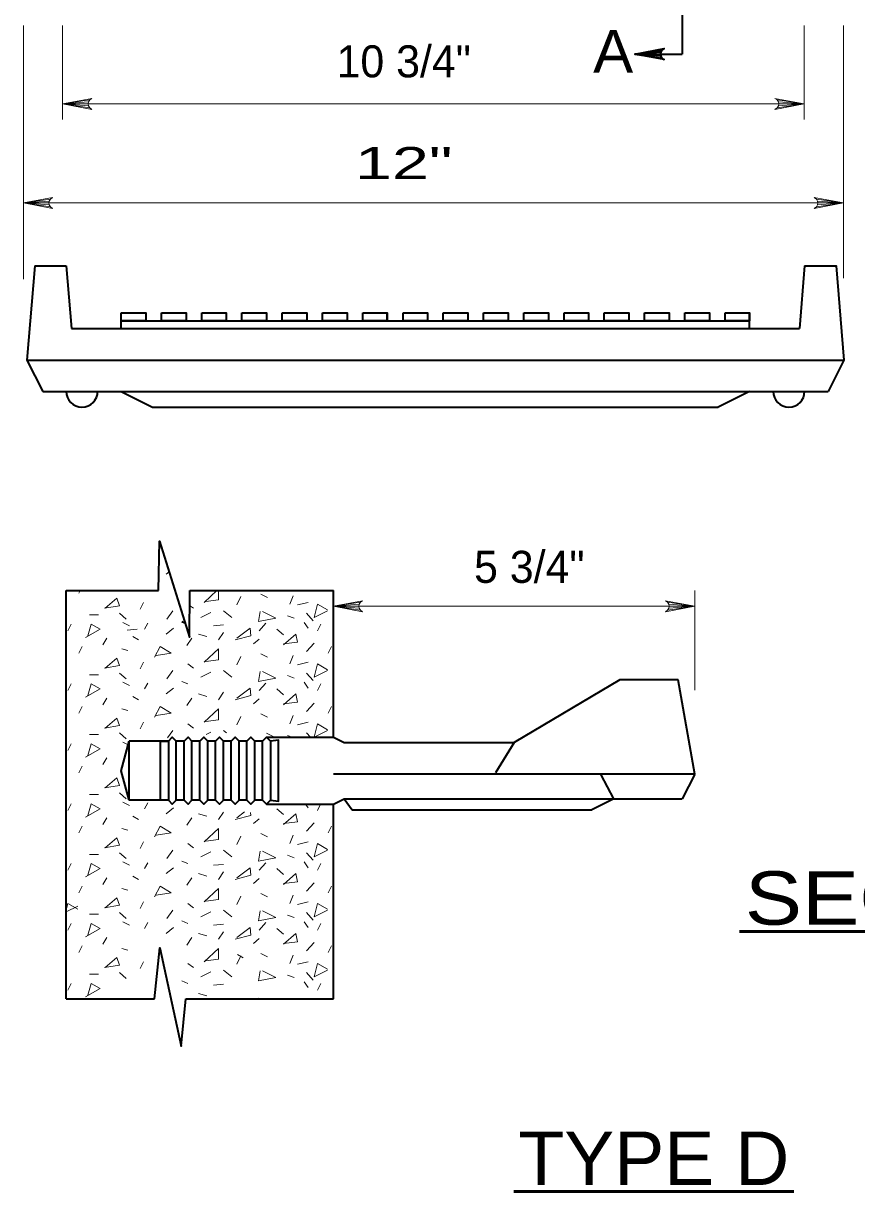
# Model space of a CAD drawing. Extents: x 15 to 140, y -57 to 117.
# Drawn here: x 97.08 to 123.6, y -0.87 to 36.32 of the extents above; entities that cross this region are included whole.
import ezdxf
from ezdxf.enums import TextEntityAlignment as Align

# ---------------------------------------------------------------- set-up
doc = ezdxf.new("R2010")
doc.units = 0
doc.header["$LTSCALE"] = 0.41
for name, color, linetype, lineweight in [('1', 7, 'Continuous', 35), ('10', 7, 'Continuous', 13), ('12', 7, 'Continuous', 53), ('13', 7, 'Continuous', 53), ('6', 7, 'Continuous', 13)]:
    doc.layers.add(name, color=color, linetype=linetype, lineweight=lineweight)

msp = doc.modelspace()

# ---------------------------------------------------------------- linework, layer by layer
at = {"layer": '1'}
for p, q in [((97.4464, 28.6016), (97.1964, 25.6016)), ((97.4464, 28.6016), (98.4464, 28.6016)), ((98.4464, 28.6016), (98.6131, 26.6016)), ((121.9464, 28.6016), (121.7798, 26.6016)), ((100.1964, 26.8516), (120.1964, 26.8516)), ((108.6655, 26.8516), (108.6655, 27.1016)), ((120.1964, 26.6016), (120.1964, 27.1016)), ((98.6131, 26.6016), (121.7798, 26.6016)), ((97.1964, 25.6016), (123.1964, 25.6016)), ((97.1964, 25.6016), (97.6964, 24.6016)), ((123.1964, 25.6016), (122.6964, 24.6016)), ((97.6964, 24.6016), (122.6964, 24.6016)), ((100.1964, 24.6016), (101.1964, 24.1016)), ((120.1964, 24.6016), (119.1964, 24.1016)), ((101.1964, 24.1016), (119.1964, 24.1016)), ((98.448, 5.2657), (98.448, 18.2657)), ((98.448, 18.2657), (101.3862, 18.2657)), ((102.3766, 18.2657), (106.948, 18.2657)), ((106.948, 13.5955), (106.948, 18.2657)), ((102.126, 17.2785), (102.2236, 17.2366)), ((116.0612, 15.4252), (112.698, 13.4252)), ((117.919, 15.4252), (116.0612, 15.4252)), ((118.448, 12.4252), (117.919, 15.4252)), ((100.448, 11.5907), (100.448, 13.4705)), ((101.698, 13.4705), (100.448, 13.4705)), ((101.948, 11.5907), (101.948, 13.4705)), ((102.198, 13.4705), (101.948, 13.4705)), ((102.198, 11.5907), (102.198, 13.4705)), ((102.448, 11.5907), (102.448, 13.4705)), ((102.698, 13.4705), (102.448, 13.4705)), ((102.698, 11.5907), (102.698, 13.4705)), ((102.948, 11.5907), (102.948, 13.4705)), ((103.198, 13.4705), (102.948, 13.4705)), ((103.198, 11.5907), (103.198, 13.4705)), ((103.448, 11.5907), (103.448, 13.4705)), ((103.698, 13.4705), (103.448, 13.4705)), ((103.698, 11.5907), (103.698, 13.4705)), ((103.948, 11.5907), (103.948, 13.4705)), ((104.198, 13.4705), (103.948, 13.4705)), ((104.198, 11.5907), (104.198, 13.4705)), ((104.448, 11.5907), (104.448, 13.4705)), ((104.698, 13.4705), (104.448, 13.4705)), ((104.698, 11.5907), (104.698, 13.4705)), ((104.823, 13.5955), (106.948, 13.5955)), ((112.698, 13.4252), (112.1117, 12.4577)), ((118.448, 12.4252), (106.948, 12.4252)), ((115.8694, 11.636), (115.4681, 12.3993)), ((118.448, 12.4252), (118.0533, 11.636)), ((101.698, 11.5907), (100.448, 11.5907)), ((102.198, 11.5907), (101.948, 11.5907)), ((102.698, 11.5907), (102.448, 11.5907)), ((103.198, 11.5907), (102.948, 11.5907)), ((103.698, 11.5907), (103.448, 11.5907)), ((104.198, 11.5907), (103.948, 11.5907)), ((104.698, 11.5907), (104.448, 11.5907)), ((107.2904, 11.636), (107.5482, 11.286)), ((115.8694, 11.636), (115.1694, 11.286)), ((104.823, 11.4657), (106.948, 11.4657)), ((106.948, 5.2657), (106.948, 11.4657)), ((107.5482, 11.286), (115.1694, 11.286)), ((98.448, 5.2657), (101.2527, 5.2657)), ((102.2482, 5.2657), (106.948, 5.2657))]:
    msp.add_line(p, q, dxfattribs=at)
for points in [[(121.9464, 28.6016), (122.9464, 28.6016), (123.1964, 25.6016)], [(100.1964, 26.6016), (100.1964, 26.8516), (100.1964, 27.1016)], [(100.448, 11.5907), (100.198, 12.5306), (100.448, 13.4705)], [(101.698, 13.4705), (101.823, 13.5955), (101.948, 13.4705)], [(102.198, 13.4705), (102.323, 13.5955), (102.448, 13.4705)], [(102.698, 13.4705), (102.823, 13.5955), (102.948, 13.4705)], [(103.198, 13.4705), (103.323, 13.5955), (103.448, 13.4705)], [(103.698, 13.4705), (103.823, 13.5955), (103.948, 13.4705)], [(104.198, 13.4705), (104.323, 13.5955), (104.448, 13.4705)], [(104.698, 13.4705), (104.823, 13.5955), (104.948, 13.4705)], [(106.948, 13.5955), (107.2904, 13.4252), (112.698, 13.4252)], [(101.698, 11.5907), (101.823, 11.4657), (101.948, 11.5907)], [(102.198, 11.5907), (102.323, 11.4657), (102.448, 11.5907)], [(102.698, 11.5907), (102.823, 11.4657), (102.948, 11.5907)], [(103.198, 11.5907), (103.323, 11.4657), (103.448, 11.5907)], [(103.698, 11.5907), (103.823, 11.4657), (103.948, 11.5907)], [(104.198, 11.5907), (104.323, 11.4657), (104.448, 11.5907)], [(104.698, 11.5907), (104.823, 11.4657), (104.948, 11.5907)], [(106.948, 11.4657), (107.2904, 11.636), (118.0533, 11.636)]]:
    msp.add_lwpolyline(points, dxfattribs=at)
for points in [[(100.1964, 27.1016), (100.9777, 27.1016), (100.9777, 26.8516), (100.1964, 26.8516)], [(101.4777, 27.1016), (102.259, 27.1016), (102.259, 26.8516), (101.4777, 26.8516)], [(102.759, 27.1016), (103.5403, 27.1016), (103.5403, 26.8516), (102.759, 26.8516)], [(104.0403, 27.1016), (104.8216, 27.1016), (104.8216, 26.8516), (104.0403, 26.8516)], [(105.3216, 27.1016), (106.1029, 27.1016), (106.1029, 26.8516), (105.3216, 26.8516)], [(106.6029, 27.1016), (107.3842, 27.1016), (107.3842, 26.8516), (106.6029, 26.8516)], [(107.8842, 27.1016), (108.6655, 27.1016), (108.6655, 26.8516), (107.8842, 26.8516)], [(109.1655, 27.1016), (109.9468, 27.1016), (109.9468, 26.8516), (109.1655, 26.8516)], [(110.4468, 27.1016), (111.2281, 27.1016), (111.2281, 26.8516), (110.4468, 26.8516)], [(111.7281, 27.1016), (112.5094, 27.1016), (112.5094, 26.8516), (111.7281, 26.8516)], [(113.0094, 27.1016), (113.7907, 27.1016), (113.7907, 26.8516), (113.0094, 26.8516)], [(114.2907, 27.1016), (115.072, 27.1016), (115.072, 26.8516), (114.2907, 26.8516)], [(115.572, 27.1016), (116.3533, 27.1016), (116.3533, 26.8516), (115.572, 26.8516)], [(116.8533, 27.1016), (117.6346, 27.1016), (117.6346, 26.8516), (116.8533, 26.8516)], [(118.1346, 27.1016), (118.9159, 27.1016), (118.9159, 26.8516), (118.1346, 26.8516)], [(119.4151, 27.1016), (120.1964, 27.1016), (120.1964, 26.8516), (119.4151, 26.8516)], [(101.448, 11.5907), (101.448, 13.4705), (101.698, 13.4705), (101.698, 11.5907)], [(104.948, 11.5907), (105.198, 11.5594), (105.198, 13.5017), (104.948, 13.4705)]]:
    msp.add_lwpolyline(points, close=True, dxfattribs=at)
for centre in [(98.9464, 24.6016), (121.4464, 24.6016)]:
    msp.add_arc(centre, 0.5, 180, 0, dxfattribs=at)
at = {"layer": '10', "lineweight": 35}
for p in [(118.0471, 40.3391), (116.5471, 35.3391)]:
    msp.add_line(p, (118.0471, 35.3391), dxfattribs=at)
at = {"layer": '10'}
for p, q in [((97.082, 36.2556), (97.082, 28.1747)), ((98.332, 36.2556), (98.332, 33.2556)), ((121.9346, 36.2556), (121.9346, 33.2556)), ((123.1846, 36.2556), (123.1846, 28.2123)), ((98.332, 33.7556), (121.9346, 33.7556)), ((97.082, 30.6016), (123.1846, 30.6016)), ((118.448, 15.0913), (118.448, 18.2657)), ((106.948, 17.7657), (118.448, 17.7657))]:
    msp.add_line(p, q, dxfattribs=at)
at = {"layer": '10', "lineweight": 35}
for points in [[(116.5471, 35.3391), (117.4791, 35.5139), (117.4073, 35.4641), (117.3703, 35.4016), (117.3596, 35.3391), (117.3703, 35.2766), (117.4073, 35.2141), (117.4791, 35.1644), (116.5471, 35.3391), (117.4073, 35.2141), (117.3703, 35.2766), (116.5471, 35.3391), (117.3596, 35.3391), (117.3703, 35.4016), (116.5471, 35.3391), (117.4073, 35.4641)], [(101.3862, 18.2657), (101.4157, 19.8375), (102.3652, 16.7808), (102.3766, 18.2657)], [(101.2527, 5.2657), (101.4258, 6.8915), (102.1052, 3.7637), (102.2482, 5.2657)]]:
    msp.add_lwpolyline(points, dxfattribs=at)
at = {"layer": '10'}
for points in [[(98.332, 33.7556), (99.2641, 33.9303), (99.1923, 33.8806), (99.1553, 33.8181), (99.1445, 33.7556), (99.1553, 33.6931), (99.1923, 33.6306), (99.2641, 33.5808), (98.332, 33.7556), (99.1923, 33.6306), (99.1553, 33.6931), (98.332, 33.7556), (99.1445, 33.7556), (99.1553, 33.8181), (98.332, 33.7556), (99.1923, 33.8806)], [(121.9346, 33.7556), (121.0026, 33.5808), (121.0744, 33.6306), (121.1114, 33.6931), (121.1221, 33.7556), (121.1114, 33.8181), (121.0744, 33.8806), (121.0026, 33.9303), (121.9346, 33.7556), (121.0744, 33.8806), (121.1114, 33.8181), (121.9346, 33.7556), (121.1221, 33.7556), (121.1114, 33.6931), (121.9346, 33.7556), (121.0744, 33.6306)], [(97.082, 30.6016), (98.0141, 30.7764), (97.9423, 30.7266), (97.9053, 30.6641), (97.8945, 30.6016), (97.9053, 30.5391), (97.9423, 30.4766), (98.0141, 30.4268), (97.082, 30.6016), (97.9423, 30.4766), (97.9053, 30.5391), (97.082, 30.6016), (97.8945, 30.6016), (97.9053, 30.6641), (97.082, 30.6016), (97.9423, 30.7266)], [(123.1846, 30.6016), (122.2526, 30.4268), (122.3244, 30.4766), (122.3614, 30.5391), (122.3721, 30.6016), (122.3614, 30.6641), (122.3244, 30.7266), (122.2526, 30.7764), (123.1846, 30.6016), (122.3244, 30.7266), (122.3614, 30.6641), (123.1846, 30.6016), (122.3721, 30.6016), (122.3614, 30.5391), (123.1846, 30.6016), (122.3244, 30.4766)], [(106.948, 17.7657), (107.88, 17.9404), (107.8082, 17.8907), (107.7712, 17.8282), (107.7605, 17.7657), (107.7712, 17.7032), (107.8082, 17.6407), (107.88, 17.5909), (106.948, 17.7657), (107.8082, 17.6407), (107.7712, 17.7032), (106.948, 17.7657), (107.7605, 17.7657), (107.7712, 17.8282), (106.948, 17.7657), (107.8082, 17.8907)], [(118.448, 17.7657), (117.5159, 17.5909), (117.5877, 17.6407), (117.6247, 17.7032), (117.6355, 17.7657), (117.6247, 17.8282), (117.5877, 17.8907), (117.5159, 17.9404), (118.448, 17.7657), (117.5877, 17.8907), (117.6247, 17.8282), (118.448, 17.7657), (117.6355, 17.7657), (117.6247, 17.7032), (118.448, 17.7657), (117.5877, 17.6407)]]:
    msp.add_lwpolyline(points, dxfattribs=at)
at = {"layer": '12'}
for p, q in [((119.8744, 7.4159), (137.6453, 7.4159)), ((112.6908, -0.8679), (121.6056, -0.8679))]:
    msp.add_line(p, q, dxfattribs=at)
at = {"layer": '6'}
for p, q in [((101.7187, 18.8621), (101.623, 18.7876)), ((98.8865, 18.2657), (98.843, 18.1786)), ((100.3784, 18.2657), (100.4051, 18.2581)), ((103.2428, 18.2657), (102.8408, 17.8874)), ((100.8022, 17.6756), (100.9081, 17.8874)), ((103.8734, 17.808), (104.0058, 18.0727)), ((104.6412, 18.1522), (104.853, 18.0463)), ((105.6737, 18.0992), (105.5678, 17.8345)), ((106.1503, 17.8874), (105.8061, 17.808)), ((99.1872, 17.4903), (99.4784, 17.4903)), ((100.1403, 17.5432), (100.3521, 17.3579)), ((101.8348, 17.6227), (101.6494, 17.3579)), ((102.3729, 17.7905), (102.4967, 17.7021)), ((103.0526, 17.5697), (102.7349, 17.4109)), ((103.4498, 17.6227), (103.7145, 17.4109)), ((106.0974, 17.5432), (106.3092, 17.3049)), ((98.6047, 17.199), (98.4988, 16.9872)), ((100.2462, 17.252), (100.458, 17.1461)), ((100.9346, 17.0402), (101.0405, 17.2255)), ((103.1321, 17.1461), (103.4498, 17.1726)), ((104.5882, 16.9872), (104.8, 17.2255)), ((105.4884, 17.4638), (105.7002, 17.3844)), ((106.0179, 17.252), (106.1503, 17.0667)), ((106.5474, 17.199), (106.4415, 16.9872)), ((99.6108, 16.5372), (99.7432, 16.749)), ((100.3875, 17.0054), (100.7052, 17.0319)), ((100.5639, 16.8019), (100.7493, 16.696)), ((101.8612, 17.0667), (101.623, 16.8813)), ((102.4437, 16.749), (102.2849, 16.5107)), ((102.6555, 16.8813), (102.9203, 16.8019)), ((103.2909, 16.696), (103.4498, 16.9343)), ((105.1442, 17.0402), (105.356, 16.8549)), ((98.9489, 16.4842), (98.843, 16.2724)), ((100.2197, 16.4048), (100.4051, 16.3518)), ((104.4029, 16.5636), (104.5882, 16.7225)), ((106.3356, 16.5901), (106.0974, 16.3253)), ((106.8916, 16.4842), (106.7857, 16.2724)), ((103.8734, 15.9017), (104.0058, 16.1665)), ((104.6412, 16.2459), (104.853, 16.14)), ((105.6737, 16.193), (105.5678, 15.9282)), ((100.1403, 15.637), (100.3521, 15.4516)), ((100.8022, 15.7694), (100.9081, 15.9812)), ((101.8348, 15.7164), (101.6494, 15.4516)), ((102.3113, 15.9282), (102.4967, 15.7958)), ((103.0526, 15.6635), (102.7349, 15.5046)), ((103.4498, 15.7164), (103.7145, 15.5046)), ((106.1503, 15.9812), (105.8061, 15.9017)), ((106.0974, 15.637), (106.3092, 15.3987)), ((98.6047, 15.2928), (98.4988, 15.081)), ((99.1872, 15.584), (99.4784, 15.584)), ((100.2462, 15.3457), (100.458, 15.2398)), ((100.9346, 15.1339), (101.0405, 15.3193)), ((102.126, 15.3722), (102.3113, 15.2928)), ((104.5882, 15.081), (104.8, 15.3193)), ((105.4884, 15.5576), (105.7002, 15.4781)), ((106.0179, 15.3457), (106.1503, 15.1604)), ((106.5474, 15.2928), (106.4415, 15.081)), ((100.5639, 14.8957), (100.7493, 14.7898)), ((101.8612, 15.1604), (101.623, 14.9751)), ((102.6555, 14.9751), (102.9203, 14.8957)), ((103.2909, 14.7898), (103.4498, 15.028)), ((105.1442, 15.1339), (105.356, 14.9486)), ((98.9489, 14.5779), (98.843, 14.3661)), ((99.6108, 14.6309), (99.7432, 14.8427)), ((102.4437, 14.8427), (102.2849, 14.6044)), ((104.4029, 14.6574), (104.5882, 14.8162)), ((106.3356, 14.6839), (106.0974, 14.4191)), ((106.8916, 14.5779), (106.7857, 14.3661)), ((100.2197, 14.4985), (100.4051, 14.4456)), ((103.8734, 13.9955), (104.0058, 14.2602)), ((104.6412, 14.3397), (104.853, 14.2338)), ((105.6737, 14.2867), (105.5678, 14.022)), ((100.8022, 13.8631), (100.9081, 14.0749)), ((101.8348, 13.8102), (101.6699, 13.5747)), ((102.3113, 14.022), (102.4967, 13.8896)), ((103.4498, 13.8102), (103.5444, 13.7345)), ((106.1503, 14.0749), (105.8061, 13.9955)), ((99.1872, 13.6778), (99.4784, 13.6778)), ((100.1403, 13.7307), (100.3521, 13.5454)), ((100.2462, 13.4395), (100.417, 13.3541)), ((103.0526, 13.7572), (102.8968, 13.6793)), ((105.0705, 13.5955), (104.8176, 13.722)), ((105.4884, 13.6513), (105.6372, 13.5955)), ((106.0974, 13.7307), (106.2176, 13.5955)), ((98.6047, 13.3865), (98.4988, 13.1747)), ((98.9489, 12.6717), (98.843, 12.4599)), ((99.6108, 12.7247), (99.7432, 12.9365)), ((99.1872, 11.7715), (99.4784, 11.7715)), ((100.1403, 11.8245), (100.3521, 11.6391)), ((100.2462, 11.5332), (100.458, 11.4273)), ((98.6047, 11.4803), (98.4988, 11.2685)), ((100.9346, 11.3214), (101.0405, 11.5068)), ((101.8612, 11.3479), (101.623, 11.1626)), ((102.6555, 11.1626), (102.9203, 11.0832)), ((103.2909, 10.9773), (103.4498, 11.2155)), ((104.1234, 11.2177), (103.8734, 11.0302)), ((105.1442, 11.3214), (105.356, 11.1361)), ((106.0662, 11.4657), (106.1503, 11.3479)), ((106.5401, 11.4657), (106.4415, 11.2685)), ((99.6108, 10.8184), (99.7432, 11.0302)), ((100.5639, 11.0832), (100.7493, 10.9773)), ((102.4437, 11.0302), (102.2849, 10.7919)), ((104.4029, 10.8449), (104.5882, 11.0037)), ((106.3356, 10.8714), (106.0974, 10.6066)), ((98.9489, 10.7654), (98.843, 10.5536)), ((100.2197, 10.686), (100.4051, 10.6331)), ((103.8734, 10.183), (104.0058, 10.4477)), ((104.6412, 10.5272), (104.853, 10.4213)), ((105.6737, 10.4742), (105.5678, 10.2095)), ((106.8916, 10.7654), (106.7857, 10.5536)), ((100.8022, 10.0506), (100.9081, 10.2624)), ((102.3113, 10.2095), (102.4967, 10.0771)), ((106.1503, 10.2624), (105.8061, 10.183)), ((99.1872, 9.8653), (99.4784, 9.8653)), ((100.1403, 9.9182), (100.3521, 9.7329)), ((101.8348, 9.9977), (101.6494, 9.7329)), ((103.0526, 9.9447), (102.7349, 9.7859)), ((103.4498, 9.9977), (103.7145, 9.7859)), ((105.4884, 9.8388), (105.7002, 9.7594)), ((106.0974, 9.9182), (106.3092, 9.6799)), ((98.6047, 9.574), (98.4988, 9.3622)), ((100.2462, 9.627), (100.458, 9.5211)), ((100.9346, 9.4152), (101.0405, 9.6005)), ((101.8612, 9.4417), (101.623, 9.2563)), ((102.126, 9.6535), (102.3113, 9.574)), ((103.1321, 9.5211), (103.4498, 9.5476)), ((103.2909, 9.071), (103.4498, 9.3093)), ((104.5882, 9.3622), (104.8, 9.6005)), ((105.1442, 9.4152), (105.356, 9.2299)), ((106.0179, 9.627), (106.1503, 9.4417)), ((106.5474, 9.574), (106.4415, 9.3622)), ((99.6108, 8.9122), (99.7432, 9.124)), ((100.5639, 9.1769), (100.7493, 9.071)), ((102.4437, 9.124), (102.2849, 8.8857)), ((102.6555, 9.2563), (102.9203, 9.1769)), ((104.4029, 8.9386), (104.5882, 9.0975)), ((106.3356, 8.9651), (106.0974, 8.7003)), ((98.9489, 8.8592), (98.843, 8.6474)), ((100.2197, 8.7798), (100.4051, 8.7268)), ((104.6412, 8.6209), (104.853, 8.515)), ((105.6737, 8.568), (105.5678, 8.3032)), ((106.8916, 8.8592), (106.7857, 8.6474)), ((98.8165, 8.2193), (98.448, 8.035)), ((100.8022, 8.1444), (100.9081, 8.3562)), ((102.3113, 8.3032), (102.4967, 8.1708)), ((103.8734, 8.2767), (104.0058, 8.5415)), ((106.1503, 8.3562), (105.8061, 8.2767)), ((99.1872, 7.959), (99.4784, 7.959)), ((100.1403, 8.012), (100.3521, 7.8266)), ((101.8348, 8.0914), (101.6494, 7.8266)), ((103.0526, 8.0385), (102.7349, 7.8796)), ((103.4498, 8.0914), (103.7145, 7.8796)), ((105.4884, 7.9326), (105.7002, 7.8531)), ((106.0974, 8.012), (106.3092, 7.7737)), ((98.6047, 7.6678), (98.4988, 7.456)), ((100.2462, 7.7207), (100.458, 7.6148)), ((100.9346, 7.5089), (101.0405, 7.6943)), ((101.8612, 7.5354), (101.623, 7.3501)), ((102.126, 7.7472), (102.3113, 7.6678)), ((103.1321, 7.6148), (103.4498, 7.6413)), ((104.5882, 7.456), (104.8, 7.6943)), ((105.1442, 7.5089), (105.356, 7.3236)), ((106.0179, 7.7207), (106.1503, 7.5354)), ((106.5474, 7.6678), (106.4415, 7.456)), ((99.6108, 7.0059), (99.7432, 7.2177)), ((102.4437, 7.2177), (102.2849, 6.9794)), ((102.6555, 7.3501), (102.9203, 7.2707)), ((103.2909, 7.1648), (103.4498, 7.403)), ((104.4029, 7.0324), (104.5882, 7.1912)), ((98.9489, 6.9529), (98.843, 6.7411)), ((100.2197, 6.8735), (100.4051, 6.8206)), ((104.6412, 6.7147), (104.853, 6.6088)), ((106.3356, 7.0589), (106.0974, 6.7941)), ((106.8916, 6.9529), (106.7857, 6.7411)), ((100.8022, 6.2381), (100.9081, 6.4499)), ((102.3113, 6.397), (102.4967, 6.2646)), ((103.8734, 6.3705), (104.0058, 6.6352)), ((103.8966, 6.6821), (104.0819, 6.5762)), ((105.6737, 6.6617), (105.5678, 6.397)), ((106.1503, 6.4499), (105.8061, 6.3705)), ((99.1872, 6.0528), (99.4784, 6.0528)), ((100.1403, 6.1057), (100.3521, 5.9204)), ((103.0526, 6.1322), (102.7349, 5.9734)), ((103.4498, 6.1852), (103.7145, 5.9734)), ((105.4884, 6.0263), (105.7002, 5.9469)), ((106.0974, 6.1057), (106.3092, 5.8674)), ((98.6047, 5.7615), (98.4988, 5.5497)), ((102.126, 5.841), (102.3113, 5.7615)), ((103.1321, 5.7086), (103.4498, 5.7351)), ((106.0179, 5.8145), (106.1503, 5.6292)), ((106.5474, 5.7615), (106.4415, 5.5497)), ((102.6555, 5.4438), (102.9203, 5.3644)), ((104.5657, 5.2657), (104.5882, 5.285))]:
    msp.add_line(p, q, dxfattribs=at)
for points in [[(102.8938, 17.9139), (103.2909, 17.9668), (103.2909, 18.2657)], [(99.6638, 17.7021), (100.1403, 17.7815), (100.0609, 18.0198), (99.6902, 17.7021)], [(104.6147, 17.5962), (104.5618, 17.2785), (105.1178, 17.3844), (104.6941, 17.5962)], [(106.7592, 17.6227), (106.3356, 17.4109), (106.4415, 17.8345), (106.7592, 17.6491)], [(99.0548, 16.7754), (99.5314, 17.0402), (99.2401, 17.199), (99.1342, 16.8284)], [(103.8204, 16.696), (104.3235, 16.8284), (104.297, 17.0667), (103.8734, 16.749)], [(105.356, 16.5636), (105.8061, 16.6166), (105.7532, 16.8813), (105.356, 16.5372)], [(101.2523, 16.14), (101.4376, 16.4842), (101.7818, 16.2724), (101.3053, 16.193)], [(102.8938, 16.0076), (103.2909, 16.0606), (103.2909, 16.4048), (102.8408, 15.9812)], [(99.6638, 15.7958), (100.1403, 15.8753), (100.0609, 16.1135), (99.6902, 15.7958)], [(104.6147, 15.6899), (104.5618, 15.3722), (105.1178, 15.4781), (104.6941, 15.6899)], [(106.7592, 15.7164), (106.3356, 15.5046), (106.4415, 15.9282), (106.7592, 15.7429)], [(99.0548, 14.8692), (99.5314, 15.1339), (99.2401, 15.2928), (99.1342, 14.9221)], [(103.8204, 14.7898), (104.3235, 14.9221), (104.297, 15.1604), (103.8734, 14.8427)], [(105.356, 14.6574), (105.8061, 14.7103), (105.7532, 14.9751), (105.356, 14.6309)], [(101.2523, 14.2338), (101.4376, 14.5779), (101.7818, 14.3661), (101.3053, 14.2867)], [(99.6638, 13.8896), (100.1403, 13.969), (100.0609, 14.2073), (99.6902, 13.8896)], [(102.8938, 14.1014), (103.2909, 14.1543), (103.2909, 14.4985), (102.8408, 14.0749)], [(106.7592, 13.8102), (106.3356, 13.5984), (106.4415, 14.022), (106.7592, 13.8366)], [(99.0548, 12.9629), (99.5314, 13.2277), (99.2401, 13.3865), (99.1342, 13.0159)], [(99.6638, 11.9833), (100.1403, 12.0628), (100.0609, 12.301), (99.6902, 11.9833)], [(99.0548, 11.0567), (99.5314, 11.3214), (99.2401, 11.4803), (99.1342, 11.1096)], [(103.8204, 10.9773), (104.3235, 11.1096), (104.3136, 11.1984)], [(105.356, 10.8449), (105.8061, 10.8978), (105.7532, 11.1626), (105.356, 10.8184)], [(101.2523, 10.4213), (101.4376, 10.7654), (101.7818, 10.5536), (101.3053, 10.4742)], [(102.8938, 10.2889), (103.2909, 10.3418), (103.2909, 10.686), (102.8408, 10.2624)], [(99.6638, 10.0771), (100.1403, 10.1565), (100.0609, 10.3948), (99.6902, 10.0771)], [(106.7592, 9.9977), (106.3356, 9.7859), (106.4415, 10.2095), (106.7592, 10.0241)], [(104.6147, 9.9712), (104.5618, 9.6535), (105.1178, 9.7594), (104.6941, 9.9712)], [(99.0548, 9.1504), (99.5314, 9.4152), (99.2401, 9.574), (99.1342, 9.2034)], [(103.8204, 9.071), (104.3235, 9.2034), (104.297, 9.4417), (103.8734, 9.124)], [(105.356, 8.9386), (105.8061, 8.9916), (105.7532, 9.2563), (105.356, 8.9122)], [(101.2523, 8.515), (101.4376, 8.8592), (101.7818, 8.6474), (101.3053, 8.568)], [(102.8938, 8.3826), (103.2909, 8.4356), (103.2909, 8.7798), (102.8408, 8.3562)], [(98.448, 8.0998), (98.4988, 8.3032), (98.8165, 8.1179)], [(99.6638, 8.1708), (100.1403, 8.2503), (100.0609, 8.4885), (99.6902, 8.1708)], [(106.7592, 8.0914), (106.3356, 7.8796), (106.4415, 8.3032), (106.7592, 8.1179)], [(104.6147, 8.0649), (104.5618, 7.7472), (105.1178, 7.8531), (104.6941, 8.0649)], [(99.0548, 7.2442), (99.5314, 7.5089), (99.2401, 7.6678), (99.1342, 7.2971)], [(103.8204, 7.1648), (104.3235, 7.2971), (104.297, 7.5354), (103.8734, 7.2177)], [(105.356, 7.0324), (105.8061, 7.0853), (105.7532, 7.3501), (105.356, 7.0059)], [(102.8938, 6.4764), (103.2909, 6.5293), (103.2909, 6.8735), (102.8408, 6.4499)], [(99.6638, 6.2646), (100.1403, 6.344), (100.0609, 6.5823), (99.6902, 6.2646)], [(106.7592, 6.1852), (106.3356, 5.9734), (106.4415, 6.397), (106.7592, 6.2116)], [(104.6147, 6.1587), (104.5618, 5.841), (105.1178, 5.9469), (104.6941, 6.1587)], [(99.0548, 5.3379), (99.5314, 5.6027), (99.2401, 5.7615), (99.1342, 5.3909)]]:
    msp.add_lwpolyline(points, dxfattribs=at)

# ---------------------------------------------------------------- texts
at = {"layer": '12'}
for s, height, width, p in [('A', 1.36, 1.05, (115.8529, 34.7486)), ('SECTION A-A', 1.7, 1.2, (128.7598, 7.6284)), ('TYPE D', 1.7, 1.05, (117.1482, -0.6554))]:
    msp.add_text(s, height=height, dxfattribs=dict(at, width=width)).set_placement(p, align=Align.CENTER)
at = {"layer": '13'}
for s, p in [('10 3/4"', (109.1884, 34.5997)), ('5 3/4"', (113.1847, 18.5094))]:
    msp.add_text(s, height=1.02, dxfattribs=at).set_placement(p, align=Align.CENTER)
at = {"layer": '13', "width": 1.55}
msp.add_text('12"', height=1.02, dxfattribs=at).set_placement((109.1884, 31.3629), align=Align.CENTER)

doc.saveas('drawing.dxf')
